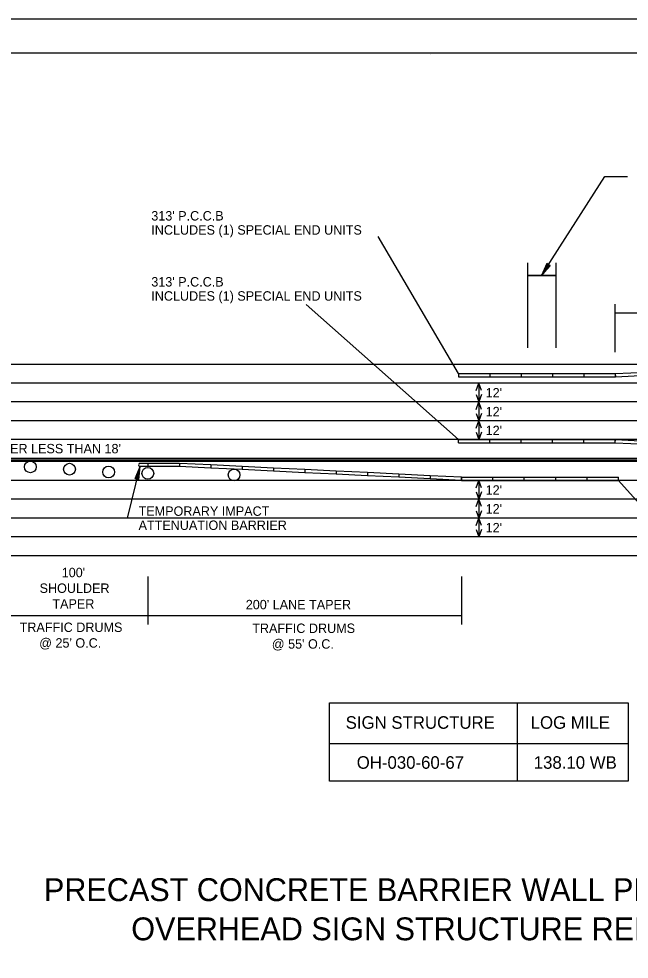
# Model space of a CAD drawing. Extents: x 1397271 to 1411271, y 376395 to 377888.
# Drawn here: x 1409762 to 1410252, y 377132 to 377888 of the extents above; entities that cross this region are included whole.
import ezdxf

# ---------------------------------------------------------------- set-up
doc = ezdxf.new("R2010")
doc.units = 0
for name, color, linetype in [('Default', 7, 'Continuous'), ('R_Border', 7, 'Continuous'), ('R_Border Notes', 7, 'Continuous'), ('R_Dimension', 7, 'Continuous'), ('R_Horz Alg', 7, 'Continuous'), ('R_MOT', 7, 'Continuous'), ('R_No Plot', 7, 'Continuous')]:
    doc.layers.add(name, color=color, linetype=linetype)

msp = doc.modelspace()

# ---------------------------------------------------------------- linework, layer by layer
at = {"layer": 'Default'}
for p, q in [((1410186.16, 377691.15), (1410181.97, 377681.57)), ((1410188.78, 377689.5), (1410181.97, 377681.57)), ((1410186.38, 377691.01), (1410182.89, 377683.03)), ((1410188.57, 377689.63), (1410182.89, 377683.03)), ((1410186.6, 377690.87), (1410183.83, 377684.53)), ((1410188.34, 377689.77), (1410183.83, 377684.53)), ((1410186.82, 377690.73), (1410184.75, 377685.99)), ((1410188.12, 377689.91), (1410184.75, 377685.99)), ((1410187.04, 377690.59), (1410185.68, 377687.48)), ((1410187.9, 377690.05), (1410185.68, 377687.48)), ((1410188.78, 377689.5), (1410186.16, 377691.15)), ((1410187.27, 377690.45), (1410186.6, 377688.94)), ((1410187.68, 377690.19), (1410186.6, 377688.94)), ((1409865.64, 377530.61), (1409859.33, 377530.61)), ((1409855.34, 377518.42), (1409859.34, 377528.09)), ((1409855.6, 377518.36), (1409858.92, 377526.41)), ((1409855.85, 377518.3), (1409858.49, 377524.69)), ((1409857.85, 377517.8), (1409858.49, 377524.69)), ((1409858.1, 377517.74), (1409858.92, 377526.41)), ((1409858.36, 377517.68), (1409859.34, 377528.09)), ((1409865.64, 377528.09), (1409859.34, 377528.09)), ((1409855.34, 377518.42), (1409858.36, 377517.68)), ((1409856.1, 377518.24), (1409858.08, 377523.01)), ((1409856.36, 377518.17), (1409857.66, 377521.31)), ((1409856.61, 377518.11), (1409857.24, 377519.64)), ((1409857.09, 377517.99), (1409857.24, 377519.64)), ((1409857.34, 377517.93), (1409857.66, 377521.31)), ((1409857.6, 377517.86), (1409858.08, 377523.01))]:
    msp.add_line(p, q, dxfattribs=at)
msp.add_arc((1409859.25, 377529.35), 1.26, 86.19353, 274.03717, dxfattribs=at)
at = {"layer": 'R_Border'}
for p, q in [((1409024.85, 377860.72), (1411238.15, 377860.72)), ((1410092.5, 377858.9), (1410092.5, 377858.9)), ((1410092.5, 377858.9), (1410092.5, 377858.9))]:
    msp.add_line(p, q, dxfattribs=at)
at = {"layer": 'R_Border Notes'}
for p, q in [((1410162.34, 377338.06), (1410162.34, 377275.11)), ((1410011.55, 377305.48), (1410251.44, 377305.48))]:
    msp.add_line(p, q, dxfattribs=at)
msp.add_lwpolyline([(1410011.55, 377338.06), (1410251.44, 377338.06), (1410251.44, 377275.11), (1410011.55, 377275.11)], close=True, dxfattribs=at)
at = {"layer": 'R_Dimension'}
for p, q in [((1410115.14, 377602.75), (1410050.67, 377713.11)), ((1410170.62, 377691.78), (1410170.62, 377623.41)), ((1410193.32, 377691.78), (1410193.32, 377623.41)), ((1410170.62, 377681.57), (1410193.32, 377681.57)), ((1410193.32, 377681.57), (1410170.62, 377681.57)), ((1410115.14, 377549.68), (1409992.65, 377658.19)), ((1410241.2, 377620), (1410241.2, 377658.53)), ((1410241.2, 377651.67), (1410619.31, 377651.67)), ((1410129.35, 377589.15), (1410131.5, 377595.07)), ((1410131.5, 377595.07), (1410131.5, 377549.68)), ((1410133.67, 377589.16), (1410131.5, 377595.07)), ((1410129.33, 377585.86), (1410131.5, 377579.94)), ((1410133.64, 377585.87), (1410131.5, 377579.94)), ((1410129.35, 377574.02), (1410131.5, 377579.94)), ((1410133.67, 377574.02), (1410131.5, 377579.94)), ((1410129.33, 377570.73), (1410131.5, 377564.81)), ((1410133.64, 377570.74), (1410131.5, 377564.81)), ((1410129.35, 377558.88), (1410131.5, 377564.81)), ((1410133.67, 377558.89), (1410131.5, 377564.81)), ((1410129.33, 377555.6), (1410131.5, 377549.68)), ((1410133.64, 377555.61), (1410131.5, 377549.68)), ((1410129.35, 377510.97), (1410131.5, 377516.9)), ((1410131.5, 377516.9), (1410131.5, 377471.51)), ((1410133.67, 377510.98), (1410131.5, 377516.9)), ((1410341.02, 377408.39), (1410243.75, 377516.9)), ((1410129.33, 377507.69), (1410131.5, 377501.77)), ((1410129.35, 377495.84), (1410131.5, 377501.77)), ((1410133.64, 377507.7), (1410131.5, 377501.77)), ((1410133.67, 377495.85), (1410131.5, 377501.77)), ((1410129.33, 377492.56), (1410131.5, 377486.64)), ((1410129.35, 377480.71), (1410131.5, 377486.64)), ((1410133.64, 377492.57), (1410131.5, 377486.64)), ((1410133.67, 377480.72), (1410131.5, 377486.64)), ((1410129.33, 377477.43), (1410131.5, 377471.51)), ((1410133.64, 377477.44), (1410131.5, 377471.51)), ((1409865.61, 377439.66), (1409865.61, 377401.14)), ((1410117.63, 377439.66), (1410117.63, 377401.14)), ((1410117.63, 377407.99), (1409739.52, 377407.99))]:
    msp.add_line(p, q, dxfattribs=at)
for points in [[(1410181.97, 377681.57), (1410232.73, 377761.21), (1410251.05, 377761.21)], [(1409982.99, 377486.64), (1409849.07, 377486.64), (1409859.34, 377528.09)]]:
    msp.add_lwpolyline(points, dxfattribs=at)
at = {"layer": 'R_Horz Alg'}
for p, q in [((1410679.99, 377610.21), (1409657.93, 377610.21)), ((1410679.99, 377595.07), (1409657.93, 377595.07)), ((1410679.99, 377579.94), (1409657.93, 377579.94)), ((1410679.99, 377564.81), (1409657.93, 377564.81)), ((1410679.99, 377549.68), (1409657.93, 377549.68)), ((1409991.58, 377534.55), (1409657.93, 377534.55)), ((1410679.99, 377533.29), (1409657.93, 377533.29)), ((1409991.58, 377532.03), (1409657.93, 377532.03)), ((1410266.45, 377534.55), (1409991.58, 377534.55)), ((1410266.45, 377532.03), (1409991.58, 377532.03)), ((1410679.99, 377516.9), (1409657.93, 377516.9)), ((1410679.99, 377501.77), (1409657.93, 377501.77)), ((1410679.99, 377486.64), (1409657.93, 377486.64)), ((1410679.99, 377471.51), (1409657.93, 377471.51)), ((1410679.99, 377456.38), (1409657.93, 377456.38))]:
    msp.add_line(p, q, dxfattribs=at)
at = {"layer": 'R_MOT'}
for p, q in [((1410115.14, 377602.75), (1410140.36, 377602.75)), ((1410115.14, 377602.75), (1410115.14, 377600.23)), ((1410115.14, 377600.23), (1410140.36, 377600.23)), ((1410140.36, 377602.75), (1410140.36, 377600.23)), ((1410140.36, 377602.75), (1410165.58, 377602.75)), ((1410140.36, 377602.75), (1410140.36, 377600.23)), ((1410140.36, 377600.23), (1410165.58, 377600.23)), ((1410165.58, 377602.75), (1410165.58, 377600.23)), ((1410165.58, 377602.75), (1410190.79, 377602.75)), ((1410165.58, 377602.75), (1410165.58, 377600.23)), ((1410165.58, 377600.23), (1410190.79, 377600.23)), ((1410190.79, 377602.75), (1410190.79, 377600.23)), ((1410190.79, 377602.75), (1410216.01, 377602.75)), ((1410190.79, 377602.75), (1410190.79, 377600.23)), ((1410190.79, 377600.23), (1410216.01, 377600.23)), ((1410216.01, 377602.75), (1410216.01, 377600.23)), ((1410216.01, 377602.75), (1410241.23, 377602.75)), ((1410216.01, 377602.75), (1410216.01, 377600.23)), ((1410216.01, 377600.23), (1410241.23, 377600.23)), ((1410241.23, 377602.75), (1410266.42, 377603.99)), ((1410241.23, 377602.75), (1410241.23, 377600.23)), ((1410241.23, 377602.75), (1410241.35, 377600.23)), ((1410241.35, 377600.23), (1410266.54, 377601.47)), ((1410115.14, 377549.68), (1410140.36, 377549.68)), ((1410115.14, 377547.16), (1410115.14, 377549.68)), ((1410115.14, 377547.16), (1410140.36, 377547.16)), ((1410140.36, 377547.16), (1410140.36, 377549.68)), ((1410140.36, 377549.68), (1410165.58, 377549.68)), ((1410140.36, 377547.16), (1410140.36, 377549.68)), ((1410140.36, 377547.16), (1410165.58, 377547.16)), ((1410165.58, 377547.16), (1410165.58, 377549.68)), ((1410165.58, 377549.68), (1410190.79, 377549.68)), ((1410165.58, 377547.16), (1410165.58, 377549.68)), ((1410165.58, 377547.16), (1410190.79, 377547.16)), ((1410190.79, 377547.16), (1410190.79, 377549.68)), ((1410190.79, 377549.68), (1410216.01, 377549.68)), ((1410190.79, 377547.16), (1410190.79, 377549.68)), ((1410190.79, 377547.16), (1410216.01, 377547.16)), ((1410216.01, 377547.16), (1410216.01, 377549.68)), ((1410216.01, 377549.68), (1410241.23, 377549.68)), ((1410216.01, 377547.16), (1410216.01, 377549.68)), ((1410216.01, 377547.16), (1410241.23, 377547.16)), ((1410241.23, 377547.16), (1410241.23, 377549.68)), ((1410241.23, 377547.16), (1410241.35, 377549.68)), ((1410241.23, 377547.16), (1410266.42, 377545.92)), ((1410241.35, 377549.68), (1410266.54, 377548.44)), ((1409890.86, 377530.61), (1409865.64, 377530.61)), ((1409865.64, 377530.61), (1409865.64, 377528.09)), ((1409890.86, 377530.61), (1409890.86, 377528.09)), ((1409890.98, 377530.61), (1409890.86, 377528.09)), ((1409916.17, 377529.36), (1409890.98, 377530.61)), ((1409890.86, 377528.09), (1409865.64, 377528.09)), ((1409916.04, 377526.85), (1409890.86, 377528.09)), ((1409916.17, 377529.36), (1409916.04, 377526.85)), ((1409916.17, 377529.36), (1409916.04, 377526.85)), ((1409941.23, 377525.6), (1409916.04, 377526.85)), ((1409941.36, 377528.12), (1409916.17, 377529.36)), ((1409941.36, 377528.12), (1409941.23, 377525.6)), ((1409941.36, 377528.12), (1409941.23, 377525.6)), ((1409966.42, 377524.36), (1409941.23, 377525.6)), ((1409966.54, 377526.88), (1409941.36, 377528.12)), ((1409966.54, 377526.88), (1409966.42, 377524.36)), ((1409966.54, 377526.88), (1409966.42, 377524.36)), ((1409991.61, 377523.12), (1409966.42, 377524.36)), ((1409991.73, 377525.64), (1409966.54, 377526.88)), ((1409991.73, 377525.64), (1409991.61, 377523.12)), ((1409991.73, 377525.64), (1409991.61, 377523.12)), ((1410016.79, 377521.87), (1409991.61, 377523.12)), ((1410016.92, 377524.39), (1409991.73, 377525.64)), ((1410016.92, 377524.39), (1410016.79, 377521.87)), ((1410016.92, 377524.39), (1410016.79, 377521.87)), ((1410042.1, 377523.15), (1410016.92, 377524.39)), ((1410042.1, 377523.15), (1410041.98, 377520.63)), ((1410042.1, 377523.15), (1410041.98, 377520.63)), ((1410067.29, 377521.91), (1410042.1, 377523.15)), ((1410041.98, 377520.63), (1410016.79, 377521.87)), ((1410067.17, 377519.39), (1410041.98, 377520.63)), ((1410067.29, 377521.91), (1410067.17, 377519.39)), ((1410067.29, 377521.91), (1410067.17, 377519.39)), ((1410092.35, 377518.15), (1410067.17, 377519.39)), ((1410092.48, 377520.67), (1410067.29, 377521.91)), ((1410092.48, 377520.67), (1410092.35, 377518.15)), ((1410092.48, 377520.67), (1410092.35, 377518.15)), ((1410117.54, 377516.9), (1410092.35, 377518.15)), ((1410117.66, 377519.42), (1410092.48, 377520.67)), ((1410117.66, 377519.42), (1410117.54, 377516.9)), ((1410117.66, 377519.42), (1410142.88, 377519.42)), ((1410117.66, 377516.9), (1410117.66, 377519.42)), ((1410117.66, 377516.9), (1410142.88, 377516.9)), ((1410142.88, 377519.42), (1410168.1, 377519.42)), ((1410142.88, 377516.9), (1410142.88, 377519.42)), ((1410142.88, 377516.9), (1410142.88, 377519.42)), ((1410142.88, 377516.9), (1410168.1, 377516.9)), ((1410168.1, 377519.42), (1410193.32, 377519.42)), ((1410168.1, 377516.9), (1410168.1, 377519.42)), ((1410168.1, 377516.9), (1410168.1, 377519.42)), ((1410168.1, 377516.9), (1410193.32, 377516.9)), ((1410193.32, 377519.42), (1410218.53, 377519.42)), ((1410193.32, 377516.9), (1410193.32, 377519.42)), ((1410193.32, 377516.9), (1410193.32, 377519.42)), ((1410193.32, 377516.9), (1410218.53, 377516.9)), ((1410218.53, 377516.9), (1410218.53, 377519.42)), ((1410218.53, 377519.42), (1410243.75, 377519.42)), ((1410218.53, 377516.9), (1410218.53, 377519.42)), ((1410218.53, 377516.9), (1410243.75, 377516.9)), ((1410243.75, 377516.9), (1410243.75, 377519.42))]:
    msp.add_line(p, q, dxfattribs=at)
for centre in [(1409771.11, 377527.79), (1409802.57, 377525.91), (1409834.01, 377523.66), (1409865.52, 377522.56), (1409934.85, 377521.29)]:
    msp.add_circle(centre, 4.73, dxfattribs=at)
at = {"layer": 'R_No Plot'}
msp.add_line((1408938.04, 377887.98), (1411271.41, 377887.98), dxfattribs=at)
for points in [[(1408937.99, 377887.98), (1411271.41, 377887.98), (1411271.41, 376394.59), (1408937.99, 376394.59)], [(1410662.32, 377860.72), (1410662.32, 377791.56), (1410912.44, 377791.56), (1410912.44, 377771.12), (1411074.84, 377771.12), (1411074.84, 377600.79), (1411238.15, 377600.79), (1411238.15, 376422.47), (1409024.85, 376422.47), (1409024.85, 377860.72)]]:
    msp.add_lwpolyline(points, close=True, dxfattribs=at)

# ---------------------------------------------------------------- texts
at = {"layer": 'Default'}
for s, height, p in [('SIGN STRUCTURE', 10.087, (1410024.52, 377317.24)), ('LOG MILE', 10.087, (1410173.21, 377317.24)), ('OH-030-60-67', 10.087, (1410033.41, 377285.1)), ('138.10 WB', 10.087, (1410175.67, 377285.1)), ('PRECAST CONCRETE BARRIER WALL PLACEMENT FOR', 18.3753, (1409782.03, 377178.71)), ('OVERHEAD SIGN STRUCTURE REPLACEMENT', 18.3753, (1409852.2, 377147.21))]:
    msp.add_text(s, height=height, dxfattribs=at).set_placement(p)
at = {"layer": 'R_Border'}
for s, p in [("313' P.C.C.B", (1409868.31, 377725.83)), ('INCLUDES (1) SPECIAL END UNITS', (1409868.31, 377714.48)), ("313' P.C.C.B", (1409868.31, 377672.76)), ('INCLUDES (1) SPECIAL END UNITS', (1409868.31, 377661.41)), ('TEMPORARY IMPACT', (1409858.09, 377488.44)), ('ATTENUATION BARRIER', (1409858.09, 377477.1))]:
    msp.add_text(s, height=7.5652, dxfattribs=at).set_placement(p)
at = {"layer": 'R_Dimension'}
for s, height, p in [("12'", 7.565, (1410137.02, 377583.58)), ("12'", 7.565, (1410137.02, 377568.45)), ("12'", 7.565, (1410137.02, 377553.32)), ("INSIDE SHOULDER LESS THAN 18'", 7.5652, (1409676.11, 377538.68)), ("12'", 7.565, (1410137.02, 377505.41)), ("12'", 7.565, (1410137.02, 377490.28)), ("12'", 7.565, (1410137.02, 377475.15)), ("100'", 7.565, (1409796.32, 377439.09)), ('SHOULDER', 7.565, (1409778.54, 377426.48)), ('TAPER', 7.565, (1409788.84, 377413.87)), ("200' LANE TAPER", 7.5652, (1409944.26, 377413.31)), ('TRAFFIC DRUMS ', 7.5652, (1409762.49, 377395.08)), ('TRAFFIC DRUMS ', 7.5652, (1409949.44, 377394.27)), ("@ 25' O.C.", 7.565, (1409778.22, 377382.47)), ("@ 55' O.C.", 7.565, (1409965.17, 377381.66))]:
    msp.add_text(s, height=height, dxfattribs=at).set_placement(p)

doc.saveas('drawing.dxf')
